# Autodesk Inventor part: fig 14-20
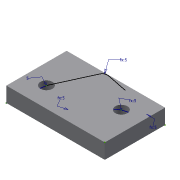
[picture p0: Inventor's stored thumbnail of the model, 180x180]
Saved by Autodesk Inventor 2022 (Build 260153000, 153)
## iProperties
Created: 2005-04
Part Number: fig 14-20
Document SubType Name: Modeling
Designer: CADCIM
Density: 1 g/cm^3
Material: Generic
Appearance: Default
Author: CADCIM
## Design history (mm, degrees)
sketch "Sketch1"
  geometry: L1 (-34.758, -22.218)-(30.545, -22.218); L2 (30.545, -22.218)-(30.545, 17.782); L3 (30.545, 17.782)-(-34.758, 17.782); L4 (-34.758, 17.782)-(-34.758, -22.218)
  constraints: 8 end point, 2 parallel, 1 horizontal, 1 perpendicular
  dimensions: "d0" = 65.30359 distance of L2.end L3.end; "d1" = 40 distance of L1.end L2.end
extrude "Extrusion1" new body sketch "Sketch1" distance "d2" = 10; taper "d3" = 0 deg
hole "Hole1" diameter "d13" = 8; stored, may be unused: countersink angle "d17" = 90 deg, drill point angle "d19" = 118 deg; dims "d11" = 13.458, "d12" = 13.14, "d14" = 6, "d15" = 4, "d16" = 2, "d18" = 15
hole "Hole2" diameter "d22" = 8; stored, may be unused: countersink angle "d26" = 90 deg, drill point angle "d28" = 118 deg; dims "d20" = 13.299, "d21" = 15.705, "d23" = 6, "d24" = 4, "d25" = 2, "d27" = 15
sketch "3D Sketch2" dims "d29" = 5, "d30" = 5 (= d29), "d31" = 5 (= d29), "d32" = 5 (= d29), "d33" = 5 (= d29)
body "Solid1"
other parameters: "LEN" = 1 [user parameter]
